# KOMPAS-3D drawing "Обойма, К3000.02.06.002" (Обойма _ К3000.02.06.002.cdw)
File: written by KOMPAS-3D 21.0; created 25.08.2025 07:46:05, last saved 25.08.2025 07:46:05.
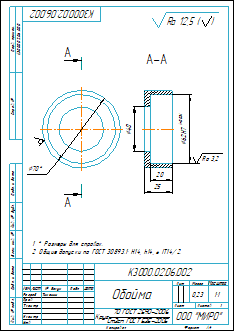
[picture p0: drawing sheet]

Sheet 1: A4, portrait

Document properties: Автор: Lutik; Полное имя файла: C:\Users\Lutik\Yandex.Disk\Документы\Новая папка\Бабка задняя\2D\Обойма подшипника_К3000.02.06.000\Обойма _ К3000.02.06.002.cdw; Знак неуказанной шероховатости: 4; Параметр неуказанной шероховатости: Ra 12,5; Масса: 0.231941

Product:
- Part/product: Обойма  | designation К3000.02.06.002
    Материал: Круг$d70 ГОСТ 2590-2006;Ст3сп ГОСТ 535-2005$ (density 7850 kg/m3)
    Масса: 0.231941

Title block, sheet 1: Наименование: Обойма; designation: К3000.02.06.002; Материал: Круг 70 ГОСТ 2590-2006 Ст3сп ГОСТ 535-2005; Масса: 0,23; Количество листов документа: 1; organisation: ООО "МИРО"; Форматы листов документа: A4; Разработал: Тимонин

Views: Вид 1, Справа, Разрез А-А
Referenced files in C:\Users\Lutik\Yandex.Disk\Документы\Новая папка\Бабка задняя\3D\: Обойма_51.m3d
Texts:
  Ra 3,2
  Ra 12,5
  Ra 12,5 ( )
  К3000.02.06.002 Обойма
Dimensions and other numbers on the sheet: 70; 40; 62; 20; 25; 1:1; 1; 0,23

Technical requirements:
  * Размеры для справок.
  Общие допуски по ГОСТ 30893.1: Н14, h14, ± IT14/2.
